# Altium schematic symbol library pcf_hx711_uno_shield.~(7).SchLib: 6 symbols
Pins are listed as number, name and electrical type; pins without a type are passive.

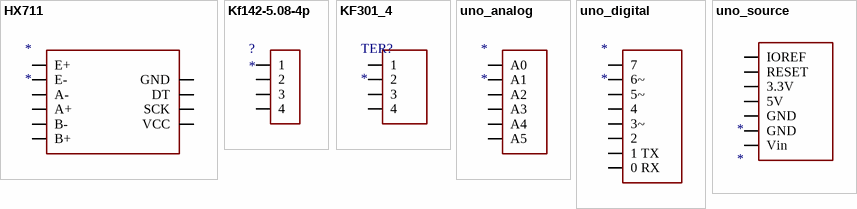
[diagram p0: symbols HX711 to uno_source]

## HX711
designator *
footprint HX711
pins: 1 E+, 2 E-, 3 A-, 4 A+, 5 B-, 6 B+, 7 GND, 8 DT, 9 SCK, 10 VCC

## Kf142-5.08-4p
designator ?
footprint Kf142-5.08-4p
pins: 1, 2, 3, 4

## KF301_4
designator TER?
footprint KF304_4
pins: 1, 2, 3, 4

## uno_analog
designator *
footprint uno_analog
pins: 0 A0, 1 A1, 2 A2, 3 A3, 4 A4, 5 A5

## uno_digital
designator *
footprint uno_digital
pins: 0 0 RX, 1 1 TX , 2, 3 3~, 4, 6 6~, 7, ?1 5~

## uno_source
designator *
footprint uno_source
pins: 0 Vin, 1 GND, 2 GND, 3 5V, 4 3.3V, 5 RESET, 6 IOREF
